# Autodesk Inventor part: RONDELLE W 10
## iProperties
Created: 2004-11
Part Number: RONDELLE W 10
Document SubType Name: Modeling
Designer: Bruno
Manufacturer: Standard
Standards Organization: Custom
Author: Bruno
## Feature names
1. Base1
